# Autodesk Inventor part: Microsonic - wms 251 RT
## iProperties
Shininess: 20.0
Length Units: 11269
Angle Units: 11279
Time Units: 11290
Mass Units: 11283
Length Display Precision: 2
Angle Display Precision: 2
Part Number: Microsonic - wms 251 RT
Material: Nylatron
Document SubType Name: Modellieren
Description: wms-251/RT
Checked By: Alves
Created: 2005-08
Designer: Tanck
Manufacturer: Standard
Standards Organization: Custom
Density: 0.0
Volumn: 0.0
Area: 0.0
PropertySet Name: Model Information
Control State: 0
Master: False
Checked Out: False
Last Check In By: Kramp
Last Check In Date: 2005-08-10
BESTELLNUMMER: wms-251/RT
ME: ST
Title: wms Sensoren
Author: Tanck
Comments: keine Bemerkung
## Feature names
1. Grundkörper mit Parabel [Extrusion]
2. Grundkörperkontur innen [Extrusion]
3. Grundkörper außen horizontal [Extrusion]
4. Grundkörper außen vertikal [Extrusion]
5. Rundung innen [Fillet]
6. Rundung Anlagefläche vertikal [Fillet]
7. Rundung Anlagefläche horizontal [Fillet]
8. Rundung Stirn außen [Fillet]
9. Nicera - Wandler [Extrusion]
10. Nicera - Wandler innen [Extrusion]
11. Rundung Nicera - Wandler [Fillet]
12. Gitter [Extrusion]
13. Steckeranschluß [Revolution]
14. Fase Steckeranschluß [Chamfer]
15. Rundung Gewindesockel [Fillet]
16. Fase Sechskant [Revolution]
17. Sechskant SW17 [Extrusion]
18. Kontaktpins [Extrusion]
19. Rundung Kontaktpins [Fillet]
20. Verdrehsicherung [Extrusion]
21. Rundung Verdrehsicherung [Fillet]
22. Auflage [Extrusion]
23. Duchgangsbohrungen [Hole]
24. Rundung Außenkörper [Fillet]
25. Stirnfläche [Extrusion]
26. Rundung Stirnfläche [Fillet]
